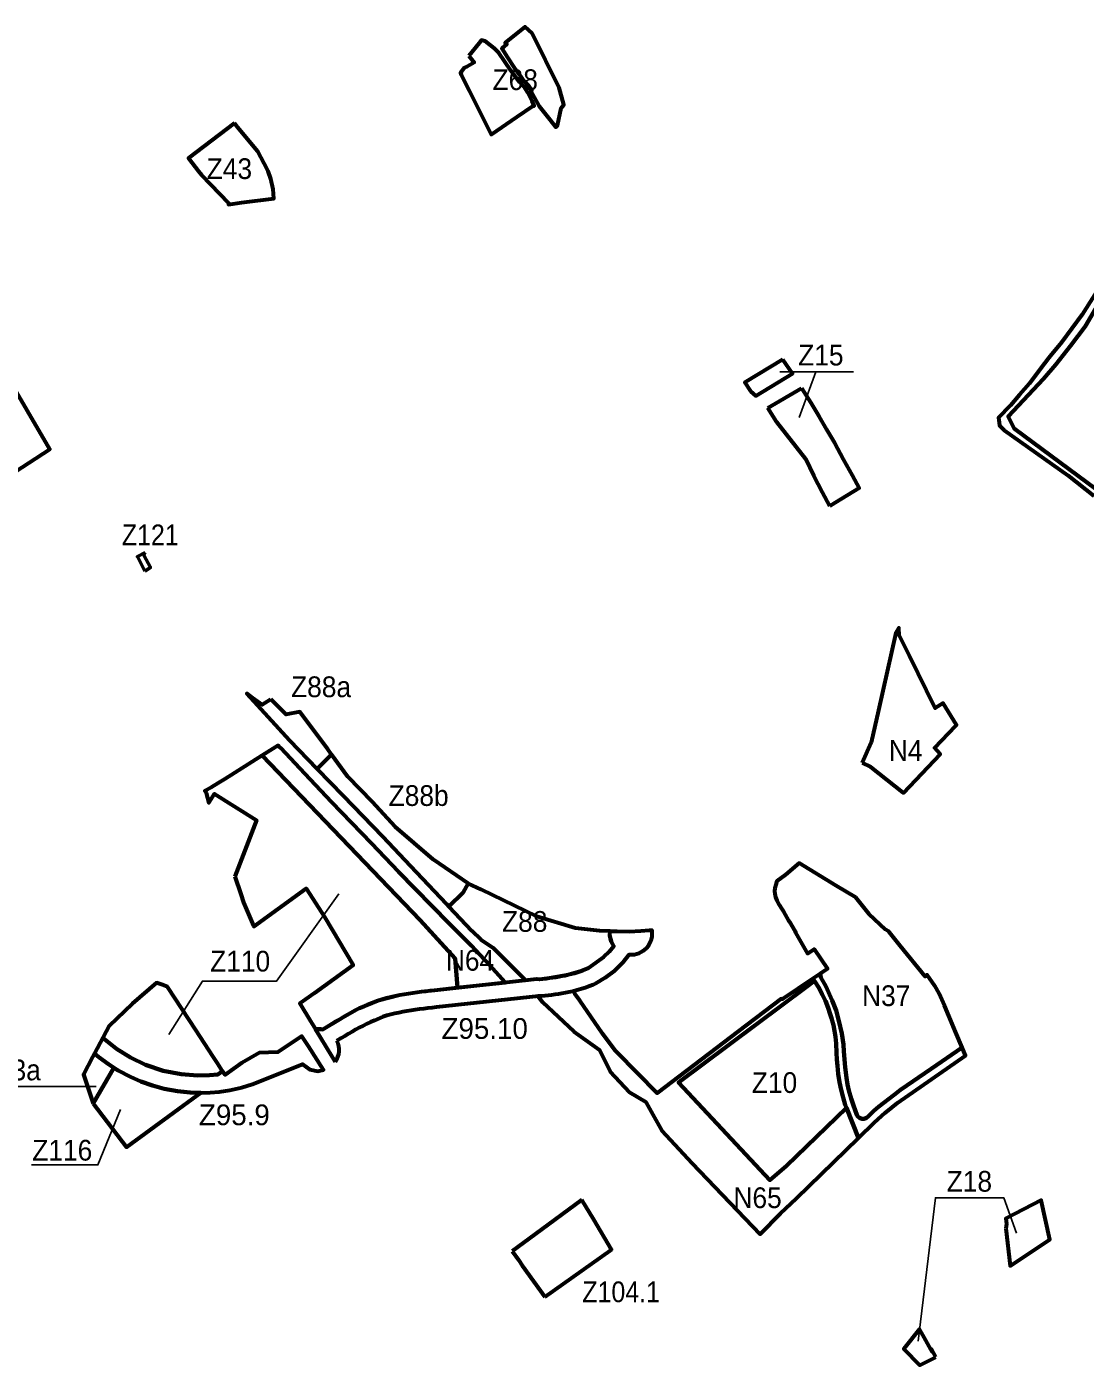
# Model space of a CAD drawing. Extents: x -650277 to -643422, y -1073980 to -1066720.
# Drawn here: x -647467 to -646242, y -1072620 to -1071070 of the extents above; entities that cross this region are included whole.
import ezdxf

# ---------------------------------------------------------------- set-up
doc = ezdxf.new("R2010")
doc.units = 0
doc.header["$LTSCALE"] = 9.6
for name, color, linetype, lineweight in [('1', 7, 'Continuous', 60), ('11', 7, 'Continuous', 60), ('15', 7, 'Continuous', 60), ('24', 7, 'Continuous', 60), ('30', 7, 'Continuous', 60), ('35', 7, 'Continuous', 60), ('40', 7, 'Continuous', 60), ('42', 7, 'Continuous', 60), ('45', 7, 'Continuous', 60), ('60', 7, 'Continuous', 60), ('63', 7, 'Continuous', 25), ('7', 7, 'Continuous', 60), ('9', 7, 'Continuous', 60)]:
    doc.layers.add(name, color=color, linetype=linetype, lineweight=lineweight)

msp = doc.modelspace()

# ---------------------------------------------------------------- linework, layer by layer
at = {"layer": '1'}
for p, q in [((-646609.21, -1071510.98), (-646570, -1071488.38)), ((-646417.787, -1072612.168), (-646414.77, -1072610.61))]:
    msp.add_line(p, q, dxfattribs=at)
for points in [[(-646591.65, -1071454.91), (-646635.79, -1071481.6), (-646629.37, -1071491.74), (-646623.18, -1071496.99), (-646580.58, -1071471.48)], [(-646606.848, -1072405.785), (-646587.666, -1072389.082), (-646518.208, -1072321.92), (-646519.417, -1072318.408), (-646522.007, -1072309.932), (-646524.282, -1072300.849), (-646526, -1072292.201), (-646527.5, -1072282.657), (-646528.566, -1072273.308), (-646529.182, -1072265.941), (-646529.607, -1072258.124), (-646530.188, -1072247.442), (-646530.892, -1072239.747), (-646531.93, -1072232.861), (-646533.286, -1072226.031), (-646535.344, -1072217.844), (-646536.772, -1072213.218), (-646539.168, -1072206.122), (-646539.168, -1072206.122), (-646542.484, -1072197.985), (-646546.09, -1072190.428), (-646549.793, -1072183.38), (-646554.56, -1072175.629), (-646555.051, -1072174.933), (-646563.299, -1072181.091), (-646710.684, -1072291.133), (-646712.634, -1072292.59)], [(-646333.34, -1072461.67), (-646328.45, -1072504.81), (-646282.47, -1072474.34), (-646292.44, -1072428.89), (-646333.33, -1072450.12), (-646332.68, -1072456.19)]]:
    msp.add_lwpolyline(points, close=True, dxfattribs=at)
for points in [[(-646570, -1071488.38), (-646559.53, -1071505.12), (-646550.23, -1071520.88), (-646541.14, -1071536.3), (-646532.04, -1071551.72), (-646521.8, -1071570.34), (-646511.47, -1071589.11), (-646503.31, -1071603.95), (-646531.2, -1071621.07), (-646537.28, -1071624.8)], [(-646537.28, -1071624.8), (-646545.89, -1071609.07), (-646555.78, -1071589.66), (-646565.17, -1071570.4), (-646598.63, -1071527.8), (-646609.21, -1071510.98)], [(-647184.81, -1071848.61), (-647185.62, -1071849.12), (-647194.96, -1071854.93), (-647205.62, -1071847.24), (-647212.66, -1071842.15), (-647163.08, -1071896.13), (-647131.146, -1071929.146)], [(-647131.146, -1071929.146), (-647114.479, -1071912.479), (-647118.79, -1071906.59), (-647151.07, -1071863.08), (-647167.15, -1071866.22), (-647184.81, -1071848.61)], [(-646996.8, -1072034.35), (-647040.89, -1071996.58), (-647067.53, -1071967.54), (-647095.51, -1071938.39), (-647114.479, -1071912.479), (-647131.146, -1071929.146), (-647101.07, -1071960.24)], [(-647101.07, -1071960.24), (-647055.16, -1072007.74), (-647023.04, -1072041.63), (-646981.35, -1072085.77), (-646978.602, -1072088.66), (-646962.041, -1072072.379), (-646956.04, -1072061.95), (-646996.8, -1072034.35)], [(-646420.36, -1072601.78), (-646427.95, -1072588.07), (-646432.57, -1072579.75), (-646433.36, -1072578.45), (-646451.458, -1072601.008), (-646433.024, -1072620.04), (-646417.787, -1072612.168)], [(-646414.77, -1072610.61), (-646419.11, -1072602.03), (-646419.47, -1072601.31), (-646419.02, -1072604.18), (-646420.36, -1072601.78)]]:
    msp.add_lwpolyline(points, dxfattribs=at)
at = {"layer": '1', "lineweight": 53}
for points in [[(-647330.34, -1071678.82), (-647339.211, -1071683.431), (-647330.73, -1071700.09)], [(-647330.73, -1071700.09), (-647324.21, -1071696.2), (-647331.65, -1071681.7), (-647330.34, -1071678.82)]]:
    msp.add_lwpolyline(points, dxfattribs=at)
at = {"layer": '11'}
msp.add_lwpolyline([(-646066.165, -1071422.155), (-646153.5, -1071383.85), (-646208.577, -1071360.044), (-646241.68, -1071416.887), (-646258.487, -1071439.265), (-646275.615, -1071460.886), (-646289.976, -1071477.514), (-646330.914, -1071521.11), (-646324, -1071535), (-646217.978, -1071613.552), (-646211.407, -1071606.247), (-646156.471, -1071545.166), (-646094.063, -1071471.007)], close=True, dxfattribs=at)
at = {"layer": '15'}
for points in [[(-646217.978, -1071613.552), (-646324, -1071535), (-646330.914, -1071521.11), (-646289.976, -1071477.514), (-646275.615, -1071460.886), (-646275.615, -1071460.886), (-646258.487, -1071439.265), (-646241.68, -1071416.887), (-646208.577, -1071360.044)], [(-646223.77, -1071369.24), (-646245.1, -1071403.04), (-646269.2, -1071435.22), (-646281.99, -1071451.4), (-646283.52, -1071453.34), (-646293.87, -1071466.43), (-646306.14, -1071482.86), (-646317.52, -1071496.12), (-646327.97, -1071508.29), (-646341.88, -1071522.81), (-646341.66, -1071524.87), (-646340.93, -1071531.64), (-646335.3, -1071537.05), (-646261.46, -1071589.38), (-646231.43, -1071613.06)]]:
    msp.add_lwpolyline(points, dxfattribs=at)
msp.add_lwpolyline([(-646529.182, -1072265.941), (-646528.566, -1072273.308), (-646527.5, -1072282.657), (-646526, -1072292.201), (-646524.282, -1072300.849), (-646522.007, -1072309.932), (-646519.417, -1072318.408), (-646518.208, -1072321.92), (-646504.244, -1072357.026), (-646485.656, -1072338.908), (-646473.069, -1072327.765), (-646465.227, -1072321.127), (-646459.03, -1072316.137), (-646380.12, -1072261.44), (-646384.056, -1072252.138), (-646420.085, -1072276.737), (-646455.557, -1072301.131), (-646462.79, -1072306.784), (-646480.923, -1072320.667), (-646486.273, -1072325.526), (-646492.813, -1072332.07), (-646494.794, -1072333.558), (-646497.569, -1072334.55), (-646500.244, -1072334.45), (-646503.018, -1072333.459), (-646504.802, -1072331.971), (-646506.189, -1072329.889), (-646509.954, -1072319.377), (-646512.729, -1072311.048), (-646515.305, -1072301.925), (-646516.692, -1072294.983), (-646518.079, -1072287.051), (-646519.756, -1072274.861), (-646521.051, -1072256.707), (-646521.646, -1072248.378), (-646523.628, -1072235.883), (-646526.798, -1072221.011), (-646530.167, -1072209.31), (-646534.527, -1072197.411), (-646541.822, -1072181.102), (-646547.606, -1072170.835), (-646548.676, -1072166.737), (-646556.693, -1072172.16), (-646555.051, -1072174.933), (-646554.56, -1072175.629), (-646549.793, -1072183.38), (-646546.09, -1072190.428), (-646542.484, -1072197.985), (-646539.168, -1072206.122), (-646536.772, -1072213.218), (-646535.344, -1072217.844), (-646533.286, -1072226.031), (-646531.93, -1072232.861), (-646530.892, -1072239.747), (-646530.188, -1072247.442), (-646529.607, -1072258.124)], close=True, dxfattribs=at)
at = {"layer": '24'}
for points in [[(-647226.41, -1072054.11), (-647219.64, -1072074.29), (-647216.23, -1072084.14), (-647204.78, -1072110.92), (-647204.38, -1072111.87), (-647143.76, -1072067.69), (-647122.33, -1072101.34), (-647089.54, -1072156.53), (-647134.17, -1072188.95), (-647151.05, -1072201.21), (-647138.65, -1072221.5), (-647133, -1072230.754), (-647124.81, -1072231.168), (-647104.989, -1072219.005), (-647082.249, -1072206.591), (-647060.973, -1072197.439), (-647035.515, -1072191.104), (-647010.148, -1072187.308), (-646995.137, -1072185.597), (-646968.503, -1072182.672), (-646971.283, -1072148.82), (-647011.762, -1072104.502), (-647194.903, -1071913.941), (-647238.1, -1071941), (-647245.71, -1071945.77), (-647253.67, -1071950.76), (-647261.12, -1071954.82), (-647259.7, -1071957.06), (-647256.53, -1071968.64), (-647253.85, -1071964.38), (-647249.92, -1071958.12), (-647201.53, -1071988.71)], [(-647390.58, -1072316.75), (-647366.505, -1072275.41), (-647372.858, -1072271.363), (-647383.813, -1072263.219), (-647389.072, -1072258.845), (-647391.3, -1072263.04), (-647401.88, -1072283.4)], [(-647390.58, -1072316.75), (-647351.86, -1072367.52), (-647269.52, -1072307.17), (-647265.793, -1072304.439), (-647271.395, -1072304.452), (-647278.108, -1072304.147), (-647292.715, -1072302.646), (-647308.157, -1072299.786), (-647321.953, -1072296.073), (-647335.382, -1072291.341), (-647347.369, -1072286.111), (-647361.521, -1072278.584), (-647366.505, -1072275.41)]]:
    msp.add_lwpolyline(points, close=True, dxfattribs=at)
msp.add_arc((-646767.624, -1072120.384), 24.428, 264.28146, 264.89913, dxfattribs=at)
at = {"layer": '30'}
for points in [[(-646824.42, -1072428.58), (-646878.91, -1072468.54), (-646905.18, -1072487.8)], [(-646867.283, -1072540.984), (-646791.569, -1072487.198), (-646790.354, -1072486.136), (-646810.77, -1072451.09), (-646824.42, -1072428.58)], [(-646905.18, -1072487.8), (-646898.1, -1072498.02), (-646893.64, -1072504.45), (-646867.283, -1072540.984)]]:
    msp.add_lwpolyline(points, dxfattribs=at)
at = {"layer": '35'}
msp.add_lwpolyline([(-647246.563, -1072270.214), (-647251.85, -1072262.12), (-647271.38, -1072232.23), (-647304.32, -1072181.81), (-647310.33, -1072179.58), (-647317.33, -1072176.99), (-647345.42, -1072201.58), (-647372.1, -1072226.89), (-647375.551, -1072233.387), (-647379.422, -1072240.675), (-647363.317, -1072253.632), (-647347.382, -1072263.623), (-647330.032, -1072271.935), (-647309.416, -1072278.875), (-647288.769, -1072283.003), (-647269.579, -1072284.489), (-647255.671, -1072284.192), (-647246.206, -1072283.328), (-647240.55, -1072279.42)], close=True, dxfattribs=at)
at = {"layer": '40'}
msp.add_lwpolyline([(-646507.28, -1072078.4), (-646530.073, -1072064.559), (-646573.05, -1072038.46), (-646588.75, -1072052.06), (-646598.827, -1072059.244), (-646599.86, -1072063.71), (-646601, -1072067.55), (-646601.42, -1072071.01), (-646601.16, -1072074.07), (-646600.8, -1072075.94), (-646600.22, -1072077.86), (-646598.67, -1072081.55), (-646595.86, -1072086.82), (-646593.13, -1072091.01), (-646591.02, -1072094.4), (-646585.08, -1072104.81), (-646583.9, -1072106.42), (-646577.41, -1072117.76), (-646577.08, -1072118.7), (-646563.11, -1072143.03), (-646555.49, -1072138.17), (-646539.94, -1072160.83), (-646548.676, -1072166.737), (-646547.606, -1072170.835), (-646541.822, -1072181.102), (-646534.527, -1072197.411), (-646530.167, -1072209.31), (-646526.798, -1072221.011), (-646523.628, -1072235.883), (-646521.646, -1072248.378), (-646521.051, -1072256.707), (-646519.756, -1072274.861), (-646518.079, -1072287.051), (-646516.692, -1072294.983), (-646515.305, -1072301.925), (-646512.729, -1072311.048), (-646509.954, -1072319.377), (-646506.189, -1072329.889), (-646504.802, -1072331.971), (-646503.018, -1072333.459), (-646500.244, -1072334.45), (-646497.569, -1072334.55), (-646494.794, -1072333.558), (-646492.813, -1072332.07), (-646486.273, -1072325.526), (-646480.923, -1072320.667), (-646462.79, -1072306.784), (-646455.557, -1072301.131), (-646420.085, -1072276.737), (-646384.056, -1072252.138), (-646391.77, -1072233.91), (-646399.6, -1072215.39), (-646404.67, -1072203.42), (-646410.68, -1072189.36), (-646415.84, -1072180.43), (-646424.56, -1072167.96), (-646426.98, -1072169.74), (-646455.75, -1072134.29), (-646468.35, -1072118.76), (-646469.41, -1072117.44), (-646472.72, -1072115.38), (-646491.69, -1072097.45)], close=True, dxfattribs=at)
at = {"layer": '42'}
msp.add_lwpolyline([(-647011.762, -1072104.502), (-646971.283, -1072148.82), (-646968.503, -1072182.672), (-646942.928, -1072179.864), (-646913.373, -1072176.618), (-646931.653, -1072156.802), (-646942.78, -1072144.74), (-646952.48, -1072134.22), (-646964.8, -1072121.83), (-646977.59, -1072108.96), (-646978.45, -1072108.09), (-647036.8, -1072048.41), (-647068.31, -1072015.68), (-647114.59, -1071967.77), (-647145.38, -1071935), (-647173.14, -1071905.45), (-647174.57, -1071904.06), (-647176.32, -1071902.3), (-647194.903, -1071913.941)], close=True, dxfattribs=at)
at = {"layer": '45'}
msp.add_lwpolyline([(-646594.606, -1072444.422), (-646575.792, -1072426.789), (-646504.244, -1072357.026), (-646518.208, -1072321.92), (-646587.666, -1072389.082), (-646606.848, -1072405.785), (-646712.634, -1072292.59), (-646563.299, -1072181.091), (-646555.051, -1072174.933), (-646556.693, -1072172.16), (-646592.2, -1072196.17), (-646593.85, -1072195.48), (-646643.55, -1072233.5), (-646737.449, -1072305.019), (-646738.951, -1072303.49), (-646758.684, -1072283.41), (-646785.958, -1072255.505), (-646800.76, -1072235.668), (-646826.893, -1072197.582), (-646832.718, -1072189.697), (-646834.279, -1072186.818), (-646833.373, -1072186.562), (-646835.538, -1072187.097), (-646839.556, -1072187.988), (-646843.569, -1072188.789), (-646847.575, -1072189.507), (-646851.567, -1072190.155), (-646855.545, -1072190.741), (-646859.506, -1072191.276), (-646863.448, -1072191.771), (-646867.371, -1072192.234), (-646871.271, -1072192.675), (-646874.517, -1072192.471), (-646875.509, -1072192.58), (-646870.21, -1072199.51), (-646833.75, -1072233.32), (-646803.98, -1072254.74), (-646791.59, -1072279.78), (-646769.24, -1072303.65), (-646750.58, -1072315.02), (-646750.12, -1072315.82), (-646742.32, -1072329.62), (-646731.82, -1072348.2), (-646696.83, -1072385.81), (-646618.158, -1072468.098)], close=True, dxfattribs=at)
at = {"layer": '60'}
msp.add_line((-646978.602, -1072088.66), (-646951.95, -1072116.84), dxfattribs=at)
for points in [[(-646790.432, -1072129.195), (-646791.977, -1072122.305), (-646791.84, -1072117.172), (-646804.27, -1072116.98), (-646832.01, -1072113.66), (-646876.83, -1072100.12), (-646941.054, -1072069.172), (-646956.04, -1072061.95), (-646962.041, -1072072.379), (-646978.602, -1072088.66)], [(-646951.95, -1072116.84), (-646941.45, -1072126.84), (-646927.14, -1072136.74), (-646891.05, -1072172.79), (-646890.044, -1072174.056), (-646876.712, -1072172.592), (-646873.495, -1072172.799), (-646862.09, -1072171.444), (-646840.102, -1072167.623), (-646825.169, -1072163.164), (-646816.74, -1072159.571), (-646799, -1072147), (-646792.58, -1072140.847), (-646787.481, -1072134.643), (-646790.432, -1072129.195)], [(-646816.74, -1072159.571), (-646799, -1072147), (-646792.58, -1072140.847), (-646787.481, -1072134.643), (-646790.343, -1072129.36), (-646791.977, -1072122.305), (-646791.84, -1072117.172), (-646783.449, -1072117.302), (-646769.668, -1072117.517), (-646756.298, -1072117), (-646746.547, -1072116.221), (-646743.596, -1072115.985), (-646743.411, -1072123.612), (-646744.554, -1072128.415), (-646747.39, -1072134.069), (-646750.164, -1072137.467), (-646753.929, -1072140.612), (-646758.736, -1072143.137), (-646763.959, -1072144.535), (-646770.057, -1072144.677), (-646777.129, -1072153.576), (-646787.223, -1072163.402), (-646797.713, -1072171.151), (-646808.466, -1072177.78)], [(-647124.81, -1072231.168), (-647113.646, -1072224.274), (-647109.342, -1072221.634), (-647104.989, -1072219.005), (-647100.583, -1072216.405), (-647096.114, -1072213.845), (-647091.574, -1072211.346), (-647086.955, -1072208.921), (-647082.249, -1072206.591), (-647077.456, -1072204.373), (-647072.72, -1072202.352), (-647060.973, -1072197.439), (-647055.906, -1072195.893), (-647050.82, -1072194.5), (-647045.722, -1072193.245), (-647040.618, -1072192.117), (-647035.515, -1072191.104), (-647030.417, -1072190.192), (-647025.33, -1072189.37), (-647020.254, -1072188.623), (-647015.192, -1072187.939), (-647010.148, -1072187.308), (-647005.124, -1072186.715), (-647000.12, -1072186.148), (-646995.137, -1072185.597), (-646876.712, -1072172.592), (-646873.495, -1072172.799), (-646869.667, -1072172.366), (-646865.866, -1072171.917), (-646862.09, -1072171.444), (-646858.343, -1072170.937), (-646854.627, -1072170.389), (-646850.941, -1072169.791), (-646847.291, -1072169.137), (-646843.678, -1072168.416), (-646840.102, -1072167.623), (-646836.573, -1072166.751), (-646833.091, -1072165.791), (-646829.66, -1072164.739), (-646826.287, -1072163.588), (-646822.975, -1072162.332), (-646819.733, -1072160.968), (-646816.74, -1072159.571)], [(-646808.466, -1072177.78), (-646811.621, -1072179.254), (-646815.549, -1072180.906), (-646819.509, -1072182.408), (-646823.496, -1072183.769), (-646827.501, -1072184.997), (-646831.517, -1072186.103), (-646835.538, -1072187.097), (-646839.556, -1072187.988), (-646843.569, -1072188.789), (-646847.575, -1072189.507), (-646851.567, -1072190.155), (-646855.545, -1072190.741), (-646859.506, -1072191.276), (-646863.448, -1072191.771), (-646867.371, -1072192.234), (-646871.271, -1072192.675), (-646874.517, -1072192.471), (-646992.937, -1072205.475), (-646997.894, -1072206.024), (-647002.826, -1072206.583), (-647007.734, -1072207.162), (-647012.612, -1072207.773), (-647017.46, -1072208.427), (-647022.278, -1072209.136), (-647027.061, -1072209.91), (-647031.807, -1072210.758), (-647036.512, -1072211.693), (-647041.174, -1072212.723), (-647045.786, -1072213.858), (-647050.344, -1072215.107), (-647054.841, -1072216.479), (-647064.868, -1072220.746), (-647069.33, -1072222.651), (-647073.611, -1072224.631), (-647077.867, -1072226.739), (-647082.102, -1072228.962), (-647086.322, -1072231.285), (-647090.531, -1072233.695), (-647094.737, -1072236.177), (-647098.944, -1072238.718), (-647103.164, -1072241.306), (-647108.131, -1072244.373)], [(-647109.812, -1072268.588), (-647110.55, -1072267.42), (-647119.07, -1072253.56), (-647128.07, -1072238.83), (-647133, -1072230.754)]]:
    msp.add_lwpolyline(points, dxfattribs=at)
msp.add_lwpolyline([(-647265.793, -1072304.439), (-647255.16, -1072304.123), (-647244.428, -1072303.192), (-647232.368, -1072301.4), (-647218.5, -1072298.335), (-647205.975, -1072294.599), (-647148.171, -1072271.47), (-647139.697, -1072277.484), (-647130.12, -1072279.44), (-647123.774, -1072277.899), (-647141.05, -1072250.54), (-647148.71, -1072238.76), (-647148.71, -1072238.76), (-647160.91, -1072246.82), (-647176.7, -1072257.24), (-647198.3, -1072258.09), (-647218.35, -1072269.67), (-647237.6, -1072283.78), (-647240.55, -1072279.42), (-647246.206, -1072283.328), (-647255.671, -1072284.192), (-647269.579, -1072284.489), (-647288.769, -1072283.003), (-647309.416, -1072278.875), (-647330.032, -1072271.935), (-647347.382, -1072263.623), (-647363.317, -1072253.632), (-647379.422, -1072240.675), (-647389.072, -1072258.845), (-647383.813, -1072263.219), (-647372.858, -1072271.363), (-647361.521, -1072278.584), (-647347.369, -1072286.111), (-647335.382, -1072291.341), (-647321.953, -1072296.073), (-647308.157, -1072299.786), (-647292.715, -1072302.646), (-647278.108, -1072304.147), (-647271.395, -1072304.452), (-647265.793, -1072304.439)], close=True, dxfattribs=at)
for start, end in [(77.44425, 96.77054), (326.23773, 25.81772)]:
    msp.add_arc((-647130.12, -1072255.012), 24.428, start, end, dxfattribs=at)
at = {"layer": '63'}
for p, q in [((-646510.087, -1071469.269), (-646595.257, -1071469.269)), ((-646572.844, -1071522.353), (-646553.419, -1071469.269)), ((-647525, -1072297), (-647387, -1072297))]:
    msp.add_line(p, q, dxfattribs=at)
for points in [[(-647303, -1072237), (-647264, -1072175), (-647178, -1072175), (-647106, -1072074)], [(-647462, -1072388), (-647385, -1072388), (-647359, -1072324)], [(-646321, -1072467), (-646336, -1072426), (-646415, -1072426), (-646435, -1072592)]]:
    msp.add_lwpolyline(points, dxfattribs=at)
at = {"layer": '7'}
for points in [[(-646453.04, -1071956.3), (-646451.87, -1071956.88), (-646409.4, -1071912.17), (-646416.2, -1071904.81), (-646391.83, -1071879.32), (-646390.732, -1071878.171), (-646405.99, -1071853.26), (-646415.46, -1071859.05), (-646445.115, -1071798.418), (-646456.96, -1071774.2), (-646457.52, -1071765.98), (-646461.09, -1071771.76), (-646480.81, -1071861.18), (-646489.34, -1071898.61), (-646499.741, -1071922.455)], [(-646499.741, -1071922.455), (-646490.111, -1071926.754), (-646453.04, -1071956.3)]]:
    msp.add_lwpolyline(points, dxfattribs=at)
at = {"layer": '9'}
for points in [[(-646881.89, -1071077.03), (-646890.12, -1071069.67), (-646913.49, -1071088.22), (-646911.58, -1071089.9), (-646917.04, -1071094.75), (-646910.53, -1071105.18), (-646902.62, -1071117.58), (-646895.56, -1071126.84), (-646892.339, -1071131.481), (-646886.78, -1071137.25), (-646882.37, -1071143.39), (-646883.63, -1071144.15), (-646873.89, -1071161.58), (-646861.58, -1071177.05), (-646854.49, -1071185.87), (-646852.86, -1071183.98), (-646848.58, -1071163.95), (-646845.39, -1071159.98), (-646850.93, -1071140.54)], [(-646955.39, -1071103.23), (-646949.12, -1071111.22), (-646957.26, -1071115.61), (-646960.72, -1071117.25), (-646964.99, -1071123.18), (-646964.43, -1071125.3), (-646955.2, -1071143.67), (-646929.64, -1071194.58), (-646899.85, -1071173.89), (-646881.68, -1071161.83), (-646879.91, -1071161.24), (-646881.97, -1071155.84), (-646887.07, -1071145.66), (-646890.59, -1071140.39), (-646896.62, -1071133.93), (-646904.64, -1071123.54), (-646906.72, -1071120.46), (-646920.54, -1071099.98), (-646925.88, -1071094.68), (-646936.51, -1071086.33), (-646940.67, -1071085.15), (-646943.47, -1071088.69)], [(-647226.895, -1071181.511), (-647280.14, -1071221.92), (-647268.52, -1071236.78), (-647265.15, -1071241.1), (-647233.34, -1071274.07), (-647233.64, -1071275.42), (-647218.75, -1071273.32), (-647181.12, -1071268.66), (-647181.99, -1071257.66), (-647184.58, -1071245.67), (-647187.68, -1071236.74), (-647192.29, -1071228.1), (-647199.82, -1071213.98), (-647223.46, -1071185.83)], [(-647497.04, -1071595.66), (-647440.67, -1071558.93), (-647492.3, -1071470), (-647495.85, -1071471.06), (-647558.654, -1071489.738)]]:
    msp.add_lwpolyline(points, close=True, dxfattribs=at)

# ---------------------------------------------------------------- texts
at = {"layer": '1'}
for s, width, p in [('Z121', 0.9, (-647357.291, -1071670.187)), ('Z88a', 0.95, (-647161.291, -1071846.187)), ('Z88b', 0.95, (-647048.291, -1071972.187))]:
    msp.add_text(s, height=24, dxfattribs=dict(at, width=width)).set_placement(p)
at = {"layer": '63'}
for s, width, p in [('Z68', 0.95, (-646928, -1071143)), ('Z43', 0.95, (-647259, -1071246)), ('Z15', 0.95, (-646574, -1071462)), ('N4', 0.95, (-646469, -1071920)), ('Z88', 0.95, (-646917, -1072118)), ('Z110', 0.95, (-647255, -1072164)), ('N64', 0.95, (-646982, -1072163)), ('N37', 0.95, (-646500, -1072204)), ('N63a', 0.95, (-647524, -1072290)), ('Z10', 0.95, (-646627.672, -1072304.645)), ('Z116', 0.95, (-647461, -1072383)), ('Z18', 0.95, (-646402, -1072419)), ('N65', 0.95, (-646649, -1072438)), ('Z104.1', 0.9, (-646824, -1072547))]:
    msp.add_text(s, height=24, dxfattribs=dict(at, width=width)).set_placement(p)
for s, p in [('Z95.10', (-646987, -1072242)), ('Z95.9', (-647268, -1072342))]:
    msp.add_text(s, height=24, dxfattribs=at).set_placement(p)

doc.saveas('drawing.dxf')
